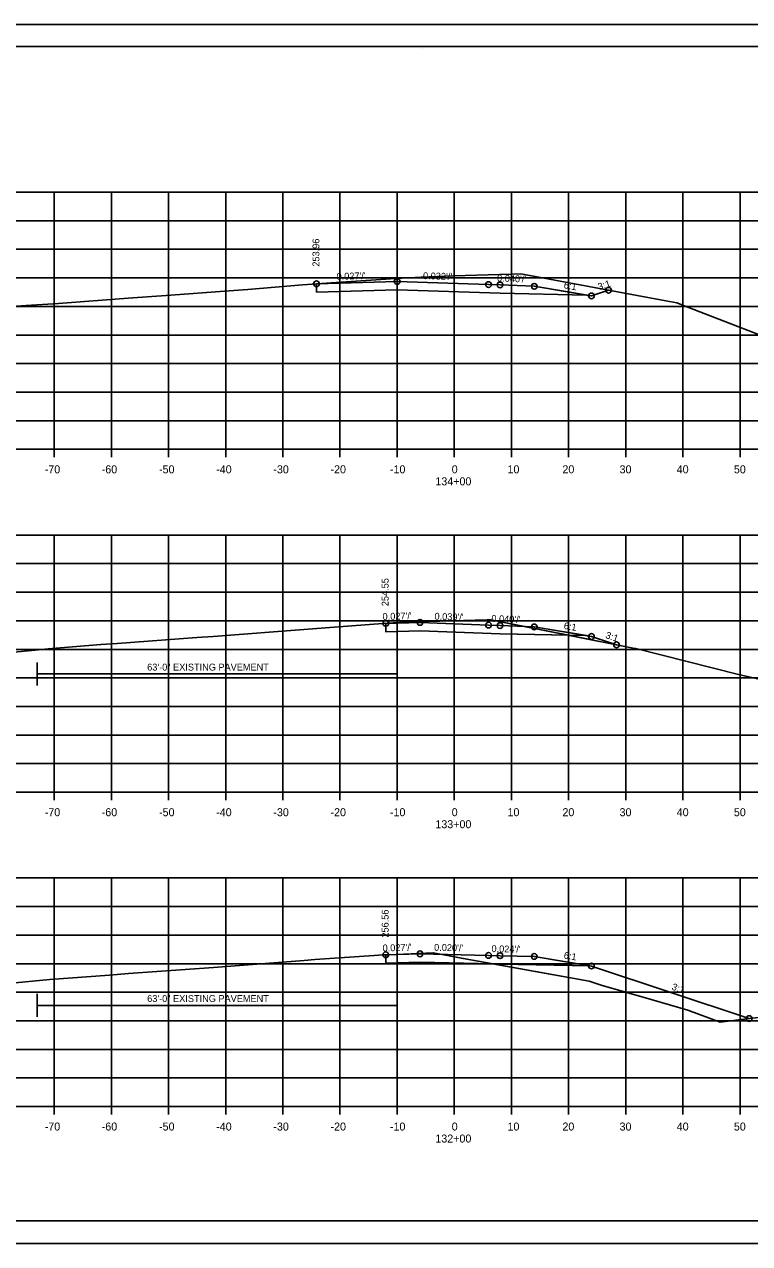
# Model space of a CAD drawing. Extents: x 1103485 to 1107180, y 2010593 to 2011873.
# Drawn here: x 1106942 to 1107068.9, y 2011446.2 to 2011659.5 of the extents above; entities that cross this region are included whole.
import ezdxf

# ---------------------------------------------------------------- set-up
doc = ezdxf.new("R2010")
doc.units = 0
for name, color, linetype in [('R_Alt Surface', 7, 'Continuous'), ('R_Axis', 7, 'Continuous'), ('R_Axis Annot', 7, 'Continuous'), ('R_Border', 7, 'Continuous'), ('R_Contours', 7, 'Continuous'), ('R_Dimension', 7, 'Continuous'), ('R_Exist Surface', 7, 'Continuous'), ('R_Fin Surface', 7, 'Continuous'), ('R_Grid', 7, 'Continuous'), ('R_No Plot', 7, 'Continuous'), ('R_Proposed Const Limits', 7, 'Continuous'), ('R_Xsect Elev', 7, 'Continuous'), ('R_Xsect Slope', 7, 'Continuous')]:
    doc.layers.add(name, color=color, linetype=linetype)

msp = doc.modelspace()

# ---------------------------------------------------------------- linework, layer by layer
at = {"layer": 'R_Alt Surface'}
for points in [[(1106993.07, 2011614.13), (1106993.07, 2011612.67), (1107007.18, 2011613.05), (1107025.18, 2011612.47), (1107040.32, 2011612.16)], [(1107005.18, 2011554.72), (1107005.18, 2011553.26), (1107011.18, 2011553.42), (1107025.18, 2011552.87), (1107040.32, 2011552.57)], [(1107005.18, 2011496.73), (1107005.18, 2011495.27), (1107011.18, 2011495.43), (1107025.18, 2011495.11), (1107040.98, 2011494.79)]]:
    msp.add_lwpolyline(points, dxfattribs=at)
at = {"layer": 'R_Axis'}
for p, q in [((1106867.18, 2011585.17), (1107167.18, 2011585.17)), ((1106947.18, 2011583.77), (1106947.18, 2011585.17)), ((1106957.18, 2011583.77), (1106957.18, 2011585.17)), ((1106967.18, 2011583.77), (1106967.18, 2011585.17)), ((1106977.18, 2011583.77), (1106977.18, 2011585.17)), ((1106987.18, 2011583.77), (1106987.18, 2011585.17)), ((1106997.18, 2011583.77), (1106997.18, 2011585.17)), ((1107007.18, 2011583.77), (1107007.18, 2011585.17)), ((1107017.18, 2011583.77), (1107017.18, 2011585.17)), ((1107027.18, 2011583.77), (1107027.18, 2011585.17)), ((1107037.18, 2011583.77), (1107037.18, 2011585.17)), ((1107047.18, 2011583.77), (1107047.18, 2011585.17)), ((1107057.18, 2011583.77), (1107057.18, 2011585.17)), ((1107067.18, 2011583.77), (1107067.18, 2011585.17)), ((1106867.18, 2011525.17), (1107167.18, 2011525.17)), ((1106947.18, 2011523.77), (1106947.18, 2011525.17)), ((1106957.18, 2011523.77), (1106957.18, 2011525.17)), ((1106967.18, 2011523.77), (1106967.18, 2011525.17)), ((1106977.18, 2011523.77), (1106977.18, 2011525.17)), ((1106987.18, 2011523.77), (1106987.18, 2011525.17)), ((1106997.18, 2011523.77), (1106997.18, 2011525.17)), ((1107007.18, 2011523.77), (1107007.18, 2011525.17)), ((1107017.18, 2011523.77), (1107017.18, 2011525.17)), ((1107027.18, 2011523.77), (1107027.18, 2011525.17)), ((1107037.18, 2011523.77), (1107037.18, 2011525.17)), ((1107047.18, 2011523.77), (1107047.18, 2011525.17)), ((1107057.18, 2011523.77), (1107057.18, 2011525.17)), ((1107067.18, 2011523.77), (1107067.18, 2011525.17)), ((1106867.18, 2011470.17), (1107167.18, 2011470.17)), ((1106947.18, 2011468.77), (1106947.18, 2011470.17)), ((1106957.18, 2011468.77), (1106957.18, 2011470.17)), ((1106967.18, 2011468.77), (1106967.18, 2011470.17)), ((1106977.18, 2011468.77), (1106977.18, 2011470.17)), ((1106987.18, 2011468.77), (1106987.18, 2011470.17)), ((1106997.18, 2011468.77), (1106997.18, 2011470.17)), ((1107007.18, 2011468.77), (1107007.18, 2011470.17)), ((1107017.18, 2011468.77), (1107017.18, 2011470.17)), ((1107027.18, 2011468.77), (1107027.18, 2011470.17)), ((1107037.18, 2011468.77), (1107037.18, 2011470.17)), ((1107047.18, 2011468.77), (1107047.18, 2011470.17)), ((1107057.18, 2011468.77), (1107057.18, 2011470.17)), ((1107067.18, 2011468.77), (1107067.18, 2011470.17))]:
    msp.add_line(p, q, dxfattribs=at)
at = {"layer": 'R_Border'}
for p, q in [((1106859.18, 2011655.63), (1107175.36, 2011655.63)), ((1107011.7, 2011655.37), (1107011.7, 2011655.37)), ((1107011.7, 2011655.37), (1107011.7, 2011655.37)), ((1107175.36, 2011450.17), (1106859.18, 2011450.17))]:
    msp.add_line(p, q, dxfattribs=at)
at = {"layer": 'R_Contours'}
for points in [[(1106993.07, 2011614.13), (1107006.87, 2011615.06), (1107011.37, 2011615.32), (1107017.04, 2011615.52), (1107019.06, 2011615.58), (1107027.12, 2011615.82), (1107028.83, 2011615.86), (1107044.17, 2011613.01), (1107041.18, 2011612.02), (1107040.32, 2011612.16), (1107025.18, 2011612.47), (1107007.18, 2011613.05), (1106993.07, 2011612.67)], [(1107005.18, 2011554.72), (1107005.45, 2011554.74), (1107009.72, 2011554.96), (1107009.91, 2011554.97), (1107010.18, 2011554.98), (1107014.66, 2011555.11), (1107022.86, 2011555.36), (1107023.23, 2011555.37), (1107024.73, 2011555.09), (1107037.14, 2011552.63), (1107025.18, 2011552.87), (1107011.18, 2011553.42), (1107005.18, 2011553.26)], [(1107037.14, 2011552.63), (1107045.57, 2011550.96), (1107041.18, 2011552.42), (1107040.82, 2011552.48), (1107040.32, 2011552.57)], [(1107005.18, 2011496.72), (1107005.74, 2011496.74), (1107013.49, 2011497.08), (1107018.42, 2011496.11), (1107023.85, 2011495.14), (1107011.18, 2011495.43), (1107005.18, 2011495.27)], [(1107023.85, 2011495.14), (1107040.77, 2011492.13), (1107042.89, 2011491.42), (1107051.6, 2011488.88), (1107058.07, 2011487.02), (1107063.73, 2011484.96), (1107068.77, 2011485.56), (1107041.18, 2011494.76), (1107040.98, 2011494.79), (1107025.18, 2011495.11)]]:
    msp.add_lwpolyline(points, close=True, dxfattribs=at)
at = {"layer": 'R_Dimension'}
for p, q in [((1106944.18, 2011547.86), (1106944.18, 2011543.86)), ((1107007.18, 2011547.86), (1107007.18, 2011543.86)), ((1106944.18, 2011545.86), (1107007.18, 2011545.86)), ((1106944.18, 2011489.87), (1106944.18, 2011485.87)), ((1107007.18, 2011489.87), (1107007.18, 2011485.87)), ((1106944.18, 2011487.87), (1107007.18, 2011487.87))]:
    msp.add_line(p, q, dxfattribs=at)
at = {"layer": 'R_Exist Surface'}
for points in [[(1106928.72, 2011609.38), (1106942.28, 2011610.31), (1106947.95, 2011610.71), (1106960.11, 2011611.59), (1106967.56, 2011612.13), (1106976.96, 2011612.83), (1106981.07, 2011613.15), (1106990.64, 2011613.96), (1107006.87, 2011615.06), (1107011.37, 2011615.32), (1107017.04, 2011615.52), (1107019.06, 2011615.58), (1107027.12, 2011615.82), (1107028.83, 2011615.86), (1107049.15, 2011612.09), (1107054.84, 2011611.03), (1107056.13, 2011610.81), (1107058.31, 2011609.94), (1107077.03, 2011602.69)], [(1106937.63, 2011549.46), (1106943.86, 2011550.04), (1106946.12, 2011550.26), (1106955.36, 2011551), (1106958.18, 2011551.22), (1106972.14, 2011552.23), (1106974.96, 2011552.43), (1106991.6, 2011553.72), (1106993.1, 2011553.83), (1106995.43, 2011554), (1107005.45, 2011554.74), (1107009.72, 2011554.96), (1107009.91, 2011554.97), (1107010.18, 2011554.98), (1107014.66, 2011555.11), (1107022.86, 2011555.36), (1107023.23, 2011555.37), (1107024.73, 2011555.09), (1107048.78, 2011550.32), (1107048.93, 2011550.29), (1107066.93, 2011545.74), (1107096.83, 2011539)], [(1106939.12, 2011491.7), (1106946.43, 2011492.39), (1106956.85, 2011493.18), (1106958.2, 2011493.28), (1106960.18, 2011493.43), (1106975.06, 2011494.52), (1106990.91, 2011495.75), (1106992.78, 2011495.9), (1107003.15, 2011496.59), (1107004.77, 2011496.7), (1107004.96, 2011496.71), (1107005.74, 2011496.74), (1107013.49, 2011497.08), (1107018.42, 2011496.11), (1107040.77, 2011492.13), (1107042.89, 2011491.42), (1107051.6, 2011488.88), (1107058.07, 2011487.02), (1107063.73, 2011484.96), (1107074.14, 2011486.21)]]:
    msp.add_lwpolyline(points, dxfattribs=at)
at = {"layer": 'R_Fin Surface'}
for points in [[(1106993.07, 2011614.13), (1107007.18, 2011614.51), (1107023.18, 2011613.99), (1107025.18, 2011613.93), (1107031.18, 2011613.69), (1107040.32, 2011612.16), (1107041.18, 2011612.02), (1107044.17, 2011613.01)], [(1106993.07, 2011614.13), (1107007.18, 2011614.51), (1107023.18, 2011613.99), (1107025.18, 2011613.93), (1107031.18, 2011613.69)], [(1107005.18, 2011554.72), (1107011.18, 2011554.88), (1107023.18, 2011554.41), (1107025.18, 2011554.33), (1107031.18, 2011554.09), (1107040.32, 2011552.57), (1107041.18, 2011552.42), (1107045.57, 2011550.96)], [(1107005.18, 2011554.72), (1107011.18, 2011554.88), (1107023.18, 2011554.41), (1107025.18, 2011554.33), (1107031.18, 2011554.09)], [(1107005.18, 2011496.73), (1107011.18, 2011496.89), (1107023.18, 2011496.62), (1107025.18, 2011496.57), (1107031.18, 2011496.43), (1107040.98, 2011494.79), (1107041.18, 2011494.76), (1107068.77, 2011485.56)], [(1107005.18, 2011496.73), (1107011.18, 2011496.89), (1107023.18, 2011496.62), (1107025.18, 2011496.57), (1107031.18, 2011496.43)]]:
    msp.add_lwpolyline(points, dxfattribs=at)
at = {"layer": 'R_Grid'}
for p, q in [((1106867.18, 2011630.17), (1107167.18, 2011630.17)), ((1106947.18, 2011585.17), (1106947.18, 2011630.17)), ((1106957.18, 2011585.17), (1106957.18, 2011630.17)), ((1106967.18, 2011585.17), (1106967.18, 2011630.17)), ((1106977.18, 2011585.17), (1106977.18, 2011630.17)), ((1106987.18, 2011585.17), (1106987.18, 2011630.17)), ((1106997.18, 2011585.17), (1106997.18, 2011630.17)), ((1107007.18, 2011585.17), (1107007.18, 2011630.17)), ((1107017.18, 2011585.17), (1107017.18, 2011630.17)), ((1107027.18, 2011585.17), (1107027.18, 2011630.17)), ((1107037.18, 2011585.17), (1107037.18, 2011630.17)), ((1107047.18, 2011585.17), (1107047.18, 2011630.17)), ((1107057.18, 2011585.17), (1107057.18, 2011630.17)), ((1107067.18, 2011585.17), (1107067.18, 2011630.17)), ((1106867.18, 2011625.17), (1107167.18, 2011625.17)), ((1106867.18, 2011620.17), (1107167.18, 2011620.17)), ((1106867.18, 2011615.17), (1107167.18, 2011615.17)), ((1106867.18, 2011610.17), (1107167.18, 2011610.17)), ((1106867.18, 2011605.17), (1107167.18, 2011605.17)), ((1106867.18, 2011600.17), (1107167.18, 2011600.17)), ((1106867.18, 2011595.17), (1107167.18, 2011595.17)), ((1106867.18, 2011590.17), (1107167.18, 2011590.17)), ((1106867.18, 2011585.17), (1107167.18, 2011585.17)), ((1106867.18, 2011570.17), (1107167.18, 2011570.17)), ((1106947.18, 2011525.17), (1106947.18, 2011570.17)), ((1106957.18, 2011525.17), (1106957.18, 2011570.17)), ((1106967.18, 2011525.17), (1106967.18, 2011570.17)), ((1106977.18, 2011525.17), (1106977.18, 2011570.17)), ((1106987.18, 2011525.17), (1106987.18, 2011570.17)), ((1106997.18, 2011525.17), (1106997.18, 2011570.17)), ((1107007.18, 2011525.17), (1107007.18, 2011570.17)), ((1107017.18, 2011525.17), (1107017.18, 2011570.17)), ((1107027.18, 2011525.17), (1107027.18, 2011570.17)), ((1107037.18, 2011525.17), (1107037.18, 2011570.17)), ((1107047.18, 2011525.17), (1107047.18, 2011570.17)), ((1107057.18, 2011525.17), (1107057.18, 2011570.17)), ((1107067.18, 2011525.17), (1107067.18, 2011570.17)), ((1106867.18, 2011565.17), (1107167.18, 2011565.17)), ((1106867.18, 2011560.17), (1107167.18, 2011560.17)), ((1106867.18, 2011555.17), (1107167.18, 2011555.17)), ((1106867.18, 2011550.17), (1107167.18, 2011550.17)), ((1106867.18, 2011545.17), (1107167.18, 2011545.17)), ((1106867.18, 2011540.17), (1107167.18, 2011540.17)), ((1106867.18, 2011535.17), (1107167.18, 2011535.17)), ((1106867.18, 2011530.17), (1107167.18, 2011530.17)), ((1106867.18, 2011525.17), (1107167.18, 2011525.17)), ((1106867.18, 2011510.17), (1107167.18, 2011510.17)), ((1106947.18, 2011470.17), (1106947.18, 2011510.17)), ((1106957.18, 2011470.17), (1106957.18, 2011510.17)), ((1106967.18, 2011470.17), (1106967.18, 2011510.17)), ((1106977.18, 2011470.17), (1106977.18, 2011510.17)), ((1106987.18, 2011470.17), (1106987.18, 2011510.17)), ((1106997.18, 2011470.17), (1106997.18, 2011510.17)), ((1107007.18, 2011470.17), (1107007.18, 2011510.17)), ((1107017.18, 2011470.17), (1107017.18, 2011510.17)), ((1107027.18, 2011470.17), (1107027.18, 2011510.17)), ((1107037.18, 2011470.17), (1107037.18, 2011510.17)), ((1107047.18, 2011470.17), (1107047.18, 2011510.17)), ((1107057.18, 2011470.17), (1107057.18, 2011510.17)), ((1107067.18, 2011470.17), (1107067.18, 2011510.17)), ((1106867.18, 2011505.17), (1107167.18, 2011505.17)), ((1106867.18, 2011500.17), (1107167.18, 2011500.17)), ((1106867.18, 2011495.17), (1107167.18, 2011495.17)), ((1106867.18, 2011490.17), (1107167.18, 2011490.17)), ((1106867.18, 2011485.17), (1107167.18, 2011485.17)), ((1106867.18, 2011480.17), (1107167.18, 2011480.17)), ((1106867.18, 2011475.17), (1107167.18, 2011475.17)), ((1106867.18, 2011470.17), (1107167.18, 2011470.17))]:
    msp.add_line(p, q, dxfattribs=at)
at = {"layer": 'R_No Plot'}
for p, q in [((1106846.78, 2011659.52), (1107180.12, 2011659.52)), ((1106846.78, 2011446.19), (1107180.12, 2011446.19))]:
    msp.add_line(p, q, dxfattribs=at)
for points in [[(1106846.78, 2011659.52), (1107180.12, 2011659.52), (1107180.12, 2011446.19), (1106846.78, 2011446.19)], [(1107093.1, 2011655.63), (1107093.1, 2011645.75), (1107128.84, 2011645.75), (1107128.84, 2011642.83), (1107152.04, 2011642.83), (1107152.04, 2011618.5), (1107175.36, 2011618.5), (1107175.36, 2011450.17), (1106859.18, 2011450.17), (1106859.18, 2011655.63)]]:
    msp.add_lwpolyline(points, close=True, dxfattribs=at)
for centre in [(1106993.07, 2011614.13), (1107007.18, 2011614.51), (1107023.18, 2011613.99), (1107025.18, 2011613.93), (1107031.18, 2011613.69), (1107041.18, 2011612.02), (1107044.17, 2011613.01), (1107005.18, 2011554.72), (1107011.18, 2011554.88), (1107023.18, 2011554.41), (1107025.18, 2011554.33), (1107031.18, 2011554.09), (1107041.18, 2011552.42), (1107045.57, 2011550.96), (1107005.18, 2011496.73), (1107011.18, 2011496.89), (1107023.18, 2011496.62), (1107025.18, 2011496.57), (1107031.18, 2011496.43), (1107041.18, 2011494.76), (1107068.77, 2011485.56)]:
    msp.add_circle(centre, 0.5, dxfattribs=at)
at = {"layer": 'R_Proposed Const Limits'}
for points in [[(1107031.18, 2011613.69), (1107041.18, 2011612.02), (1107044.17, 2011613.01)], [(1107031.18, 2011554.09), (1107041.18, 2011552.42), (1107045.57, 2011550.96)], [(1107031.18, 2011496.43), (1107041.18, 2011494.76), (1107068.77, 2011485.56)]]:
    msp.add_lwpolyline(points, dxfattribs=at)

# ---------------------------------------------------------------- texts
at = {"layer": 'R_Axis Annot'}
for s, p in [('-70', (1106945.52, 2011580.97)), ('-60', (1106955.49, 2011580.97)), ('-50', (1106965.52, 2011580.97)), ('-40', (1106975.52, 2011580.97)), ('-30', (1106985.52, 2011580.97)), ('-20', (1106995.52, 2011580.97)), ('-10', (1107005.92, 2011580.97)), ('0', (1107016.73, 2011580.97)), ('10', (1107026.49, 2011580.97)), ('20', (1107036.1, 2011580.97)), ('30', (1107046.1, 2011580.97)), ('40', (1107056.1, 2011580.97)), ('50', (1107066.1, 2011580.97)), ('134+00', (1107013.87, 2011578.87)), ('-70', (1106945.52, 2011520.97)), ('-60', (1106955.49, 2011520.97)), ('-50', (1106965.52, 2011520.97)), ('-40', (1106975.52, 2011520.97)), ('-30', (1106985.52, 2011520.97)), ('-20', (1106995.52, 2011520.97)), ('-10', (1107005.92, 2011520.97)), ('0', (1107016.73, 2011520.97)), ('10', (1107026.49, 2011520.97)), ('20', (1107036.1, 2011520.97)), ('30', (1107046.1, 2011520.97)), ('40', (1107056.1, 2011520.97)), ('50', (1107066.1, 2011520.97)), ('133+00', (1107013.87, 2011518.87)), ('-70', (1106945.52, 2011465.97)), ('-60', (1106955.49, 2011465.97)), ('-50', (1106965.52, 2011465.97)), ('-40', (1106975.52, 2011465.97)), ('-30', (1106985.52, 2011465.97)), ('-20', (1106995.52, 2011465.97)), ('-10', (1107005.92, 2011465.97)), ('0', (1107016.73, 2011465.97)), ('10', (1107026.49, 2011465.97)), ('20', (1107036.1, 2011465.97)), ('30', (1107046.1, 2011465.97)), ('40', (1107056.1, 2011465.97)), ('50', (1107066.1, 2011465.97)), ('132+00', (1107013.87, 2011463.87))]:
    msp.add_text(s, height=1.4, dxfattribs=at).set_placement(p)
at = {"layer": 'R_Dimension'}
for p in [(1106963.44, 2011546.46), (1106963.44, 2011488.47)]:
    msp.add_text('63\'-0" EXISTING PAVEMENT', height=1.2, dxfattribs=at).set_placement(p)
at = {"layer": 'R_Xsect Elev'}
for s, p in [('253.96', (1106993.57, 2011617.13)), ('254.55', (1107005.68, 2011557.72)), ('256.56', (1107005.68, 2011499.73))]:
    msp.add_text(s, height=1.2, rotation=90, dxfattribs=at).set_placement(p)
at = {"layer": 'R_Xsect Slope'}
for s, rotation, p in [("0.027'/'", 1.5466, (1106996.6, 2011614.82)), ("0.032'/'", 358.15, (1107011.69, 2011614.96)), ("0.040'/'", 357.7094, (1107024.65, 2011614.55)), ('6:1', 350.5358, (1107036.27, 2011613.35)), ('3:1', 18.4332, (1107042.52, 2011612.99)), ("0.027'/'", 1.5466, (1107004.65, 2011555.31)), ("0.039'/'", 357.7387, (1107013.7, 2011555.38)), ("0.040'/'", 357.7167, (1107023.65, 2011554.99)), ('6:1', 350.5358, (1107036.27, 2011553.75)), ('3:1', 341.5668, (1107043.54, 2011552.17)), ("0.027'/'", 1.5466, (1107004.65, 2011497.31)), ("0.020'/'", 358.6926, (1107013.64, 2011497.43)), ("0.024'/'", 358.6455, (1107023.68, 2011497.2)), ('6:1', 350.5358, (1107036.27, 2011496.09)), ('3:1', 341.5668, (1107055.14, 2011490.64))]:
    msp.add_text(s, height=1.2, rotation=rotation, dxfattribs=at).set_placement(p)

doc.saveas('drawing.dxf')
